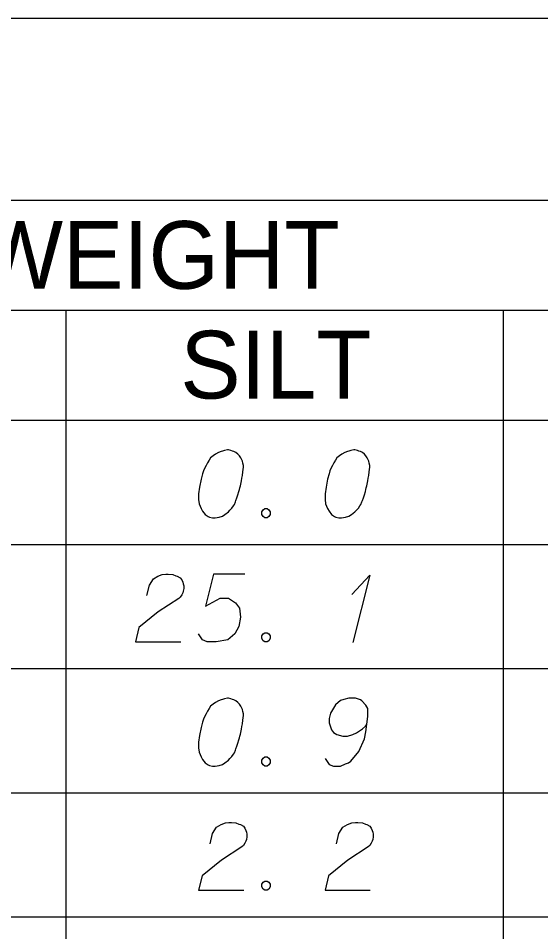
# Model space of a CAD drawing. Extents: x 2074207 to 2076812, y 516372 to 523312.
# Drawn here: x 2076584.7 to 2076621.8, y 517882.7 to 517947.4 of the extents above; entities that cross this region are included whole.
import ezdxf

# ---------------------------------------------------------------- set-up
doc = ezdxf.new("R2010")
doc.units = 0
for name, color, linetype in [('Prop DirtTable_ Soil Test Results - Outline (Major)', 7, 'Continuous'), ('Prop DirtTable_ Soil Test Results - Outline (Minor)', 7, 'Continuous'), ('Prop DirtTable_ Soil Test Results - Tx (Header - Small)', 7, 'Continuous'), ('Prop DirtTable_ Soil Test Results - Tx (Sample Data)', 7, 'Continuous')]:
    doc.layers.add(name, color=color, linetype=linetype)

msp = doc.modelspace()

# ---------------------------------------------------------------- linework, layer by layer
at = {"layer": 'Prop DirtTable_ Soil Test Results - Outline (Major)'}
for p, q in [((2076260.609, 517947.403), (2076811.903, 517947.403)), ((2076260.609, 517918.918), (2076811.903, 517918.918)), ((2076260.609, 517918.918), (2076811.903, 517918.918))]:
    msp.add_line(p, q, dxfattribs=at)
at = {"layer": 'Prop DirtTable_ Soil Test Results - Outline (Minor)'}
for p, q in [((2076260.609, 517934.518), (2076811.903, 517934.518)), ((2076526.074, 517926.718), (2076731.93, 517926.718)), ((2076588.114, 517926.718), (2076588.114, 517910.118)), ((2076619.134, 517910.118), (2076619.134, 517926.718)), ((2076260.609, 517910.118), (2076811.903, 517910.118)), ((2076260.609, 517910.118), (2076811.903, 517910.118)), ((2076588.114, 517910.118), (2076588.114, 517901.318)), ((2076619.134, 517901.318), (2076619.134, 517910.118)), ((2076260.609, 517901.318), (2076811.903, 517901.318)), ((2076260.609, 517901.318), (2076811.903, 517901.318)), ((2076588.114, 517901.318), (2076588.114, 517892.518)), ((2076619.134, 517892.518), (2076619.134, 517901.318)), ((2076260.609, 517892.518), (2076811.903, 517892.518)), ((2076260.609, 517892.518), (2076811.903, 517892.518)), ((2076588.114, 517892.518), (2076588.114, 517883.718)), ((2076619.134, 517883.718), (2076619.134, 517892.518)), ((2076260.609, 517883.718), (2076811.903, 517883.718)), ((2076260.609, 517883.718), (2076811.903, 517883.718)), ((2076588.114, 517883.718), (2076588.114, 517874.918)), ((2076619.134, 517874.918), (2076619.134, 517883.718))]:
    msp.add_line(p, q, dxfattribs=at)
at = {"layer": 'Prop DirtTable_ Soil Test Results - Tx (Sample Data)'}
for points in [[(2076599.632, 517916.807), (2076599.562, 517916.807), (2076599.35, 517916.769), (2076599.209, 517916.731), (2076599.103, 517916.693), (2076598.927, 517916.618), (2076598.715, 517916.504), (2076598.539, 517916.391), (2076598.362, 517916.24), (2076598.256, 517916.089), (2076598.151, 517915.9), (2076598.045, 517915.711), (2076597.939, 517915.484), (2076597.868, 517915.333), (2076597.798, 517915.106), (2076597.692, 517914.728), (2076597.586, 517914.161), (2076597.516, 517913.708), (2076597.516, 517913.292), (2076597.551, 517912.989), (2076597.692, 517912.649), (2076597.798, 517912.46), (2076597.974, 517912.234), (2076598.186, 517912.082), (2076598.292, 517912.045), (2076598.503, 517912.007), (2076598.68, 517912.007), (2076598.962, 517912.045), (2076599.209, 517912.12), (2076599.385, 517912.234), (2076599.632, 517912.423), (2076599.738, 517912.536), (2076599.879, 517912.687), (2076599.985, 517912.838), (2076600.055, 517912.952), (2076600.126, 517913.141), (2076600.161, 517913.216), (2076600.232, 517913.405), (2076600.302, 517913.632), (2076600.373, 517913.859), (2076600.408, 517914.01), (2076600.443, 517914.123), (2076600.479, 517914.275), (2076600.549, 517914.615), (2076600.585, 517914.804), (2076600.62, 517914.993), (2076600.655, 517915.257), (2076600.69, 517915.597), (2076600.69, 517915.711), (2076600.655, 517915.862), (2076600.62, 517916.013), (2076600.514, 517916.24), (2076600.408, 517916.391), (2076600.302, 517916.504), (2076600.161, 517916.618), (2076600.02, 517916.693), (2076599.914, 517916.731), (2076599.809, 517916.769), (2076599.632, 517916.807)], [(2076608.592, 517916.807), (2076608.522, 517916.807), (2076608.31, 517916.769), (2076608.169, 517916.731), (2076608.063, 517916.693), (2076607.887, 517916.618), (2076607.675, 517916.504), (2076607.499, 517916.391), (2076607.322, 517916.24), (2076607.216, 517916.089), (2076607.111, 517915.9), (2076607.005, 517915.711), (2076606.899, 517915.484), (2076606.828, 517915.333), (2076606.758, 517915.106), (2076606.652, 517914.728), (2076606.546, 517914.161), (2076606.476, 517913.708), (2076606.476, 517913.292), (2076606.511, 517912.989), (2076606.652, 517912.649), (2076606.758, 517912.46), (2076606.934, 517912.234), (2076607.146, 517912.082), (2076607.252, 517912.045), (2076607.463, 517912.007), (2076607.64, 517912.007), (2076607.922, 517912.045), (2076608.169, 517912.12), (2076608.345, 517912.234), (2076608.592, 517912.423), (2076608.698, 517912.536), (2076608.839, 517912.687), (2076608.945, 517912.838), (2076609.015, 517912.952), (2076609.086, 517913.141), (2076609.121, 517913.216), (2076609.192, 517913.405), (2076609.262, 517913.632), (2076609.333, 517913.859), (2076609.368, 517914.01), (2076609.403, 517914.123), (2076609.439, 517914.275), (2076609.509, 517914.615), (2076609.545, 517914.804), (2076609.58, 517914.993), (2076609.615, 517915.257), (2076609.65, 517915.597), (2076609.65, 517915.711), (2076609.615, 517915.862), (2076609.58, 517916.013), (2076609.474, 517916.24), (2076609.368, 517916.391), (2076609.262, 517916.504), (2076609.121, 517916.618), (2076608.98, 517916.693), (2076608.874, 517916.731), (2076608.769, 517916.769), (2076608.592, 517916.807)], [(2076602.207, 517912.649), (2076602.384, 517912.649), (2076602.489, 517912.574), (2076602.595, 517912.423), (2076602.595, 517912.234), (2076602.489, 517912.082), (2076602.384, 517912.007), (2076602.207, 517912.007), (2076602.101, 517912.082), (2076601.996, 517912.234), (2076601.996, 517912.423), (2076602.101, 517912.574), (2076602.207, 517912.649)], [(2076593.847, 517906.495), (2076594.023, 517907.213), (2076594.306, 517907.667), (2076594.623, 517907.856), (2076594.94, 517907.969), (2076595.187, 517908.007), (2076595.364, 517908.007), (2076595.681, 517907.969), (2076595.893, 517907.893), (2076595.999, 517907.856), (2076596.21, 517907.742), (2076596.316, 517907.591), (2076596.387, 517907.44), (2076596.422, 517907.326), (2076596.457, 517907.175), (2076596.457, 517906.986), (2076596.422, 517906.797), (2076596.387, 517906.684), (2076596.316, 517906.533), (2076596.21, 517906.382), (2076596.105, 517906.268), (2076594.658, 517905.323), (2076593.283, 517904.227), (2076593.036, 517903.207), (2076596.246, 517903.207)], [(2076600.796, 517908.007), (2076598.574, 517908.007), (2076598.009, 517905.739), (2076599.032, 517906.306), (2076599.632, 517906.306), (2076600.126, 517905.966), (2076600.408, 517905.588), (2076600.479, 517904.945), (2076600.373, 517904.303), (2076600.091, 517903.774), (2076599.597, 517903.358), (2076598.75, 517903.207), (2076598.115, 517903.207), (2076597.798, 517903.358), (2076597.516, 517903.774)], [(2076608.38, 517906.571), (2076609.65, 517907.931), (2076608.451, 517903.169)], [(2076602.207, 517903.849), (2076602.384, 517903.849), (2076602.489, 517903.774), (2076602.595, 517903.623), (2076602.595, 517903.434), (2076602.489, 517903.282), (2076602.384, 517903.207), (2076602.207, 517903.207), (2076602.101, 517903.282), (2076601.996, 517903.434), (2076601.996, 517903.623), (2076602.101, 517903.774), (2076602.207, 517903.849)], [(2076599.632, 517899.207), (2076599.562, 517899.207), (2076599.35, 517899.169), (2076599.209, 517899.131), (2076599.103, 517899.093), (2076598.927, 517899.018), (2076598.715, 517898.904), (2076598.539, 517898.791), (2076598.362, 517898.64), (2076598.256, 517898.489), (2076598.151, 517898.3), (2076598.045, 517898.111), (2076597.939, 517897.884), (2076597.868, 517897.733), (2076597.798, 517897.506), (2076597.692, 517897.128), (2076597.586, 517896.561), (2076597.516, 517896.108), (2076597.516, 517895.692), (2076597.551, 517895.389), (2076597.692, 517895.049), (2076597.798, 517894.86), (2076597.974, 517894.634), (2076598.186, 517894.482), (2076598.292, 517894.445), (2076598.503, 517894.407), (2076598.68, 517894.407), (2076598.962, 517894.445), (2076599.209, 517894.52), (2076599.385, 517894.634), (2076599.632, 517894.823), (2076599.738, 517894.936), (2076599.879, 517895.087), (2076599.985, 517895.238), (2076600.055, 517895.352), (2076600.126, 517895.541), (2076600.161, 517895.616), (2076600.232, 517895.805), (2076600.302, 517896.032), (2076600.373, 517896.259), (2076600.408, 517896.41), (2076600.443, 517896.523), (2076600.479, 517896.675), (2076600.549, 517897.015), (2076600.585, 517897.204), (2076600.62, 517897.393), (2076600.655, 517897.657), (2076600.69, 517897.997), (2076600.69, 517898.111), (2076600.655, 517898.262), (2076600.62, 517898.413), (2076600.514, 517898.64), (2076600.408, 517898.791), (2076600.302, 517898.904), (2076600.161, 517899.018), (2076600.02, 517899.093), (2076599.914, 517899.131), (2076599.809, 517899.169), (2076599.632, 517899.207)], [(2076606.476, 517894.936), (2076606.758, 517894.52), (2076607.075, 517894.407), (2076607.569, 517894.407), (2076607.922, 517894.558), (2076608.134, 517894.634), (2076608.31, 517894.747), (2076608.874, 517895.427), (2076609.262, 517896.334), (2076609.368, 517896.826), (2076609.509, 517897.922), (2076609.509, 517898.489), (2076609.368, 517898.715), (2076609.086, 517899.018), (2076608.98, 517899.093), (2076608.627, 517899.207), (2076608.169, 517899.207), (2076607.816, 517899.131), (2076607.569, 517899.056), (2076607.216, 517898.753), (2076606.864, 517898.149), (2076606.758, 517897.771), (2076606.758, 517897.468), (2076606.934, 517896.977), (2076607.075, 517896.788), (2076607.322, 517896.637), (2076607.746, 517896.523), (2076608.063, 517896.523), (2076608.451, 517896.637), (2076608.698, 517896.75), (2076609.121, 517897.052), (2076609.333, 517897.241), (2076609.439, 517897.355)], [(2076602.207, 517895.049), (2076602.384, 517895.049), (2076602.489, 517894.974), (2076602.595, 517894.823), (2076602.595, 517894.634), (2076602.489, 517894.482), (2076602.384, 517894.407), (2076602.207, 517894.407), (2076602.101, 517894.482), (2076601.996, 517894.634), (2076601.996, 517894.823), (2076602.101, 517894.974), (2076602.207, 517895.049)], [(2076598.327, 517888.895), (2076598.503, 517889.613), (2076598.786, 517890.067), (2076599.103, 517890.256), (2076599.42, 517890.369), (2076599.667, 517890.407), (2076599.844, 517890.407), (2076600.161, 517890.369), (2076600.373, 517890.293), (2076600.479, 517890.256), (2076600.69, 517890.142), (2076600.796, 517889.991), (2076600.867, 517889.84), (2076600.902, 517889.726), (2076600.937, 517889.575), (2076600.937, 517889.386), (2076600.902, 517889.197), (2076600.867, 517889.084), (2076600.796, 517888.933), (2076600.69, 517888.782), (2076600.585, 517888.668), (2076599.138, 517887.723), (2076597.763, 517886.627), (2076597.516, 517885.607), (2076600.726, 517885.607)], [(2076607.287, 517888.895), (2076607.463, 517889.613), (2076607.746, 517890.067), (2076608.063, 517890.256), (2076608.38, 517890.369), (2076608.627, 517890.407), (2076608.804, 517890.407), (2076609.121, 517890.369), (2076609.333, 517890.293), (2076609.439, 517890.256), (2076609.65, 517890.142), (2076609.756, 517889.991), (2076609.827, 517889.84), (2076609.862, 517889.726), (2076609.897, 517889.575), (2076609.897, 517889.386), (2076609.862, 517889.197), (2076609.827, 517889.084), (2076609.756, 517888.933), (2076609.65, 517888.782), (2076609.545, 517888.668), (2076608.098, 517887.723), (2076606.723, 517886.627), (2076606.476, 517885.607), (2076609.686, 517885.607)], [(2076602.207, 517886.249), (2076602.384, 517886.249), (2076602.489, 517886.174), (2076602.595, 517886.023), (2076602.595, 517885.834), (2076602.489, 517885.682), (2076602.384, 517885.607), (2076602.207, 517885.607), (2076602.101, 517885.682), (2076601.996, 517885.834), (2076601.996, 517886.023), (2076602.101, 517886.174), (2076602.207, 517886.249)]]:
    msp.add_lwpolyline(points, dxfattribs=at)

# ---------------------------------------------------------------- texts
at = {"layer": 'Prop DirtTable_ Soil Test Results - Tx (Header - Small)'}
for s, height, p in [('% BY WEIGHT', 4.79998, (2076564.009, 517928.228)), ('SILT', 4.8, (2076596.215, 517920.453))]:
    msp.add_text(s, height=height, dxfattribs=at).set_placement(p)

doc.saveas('drawing.dxf')
